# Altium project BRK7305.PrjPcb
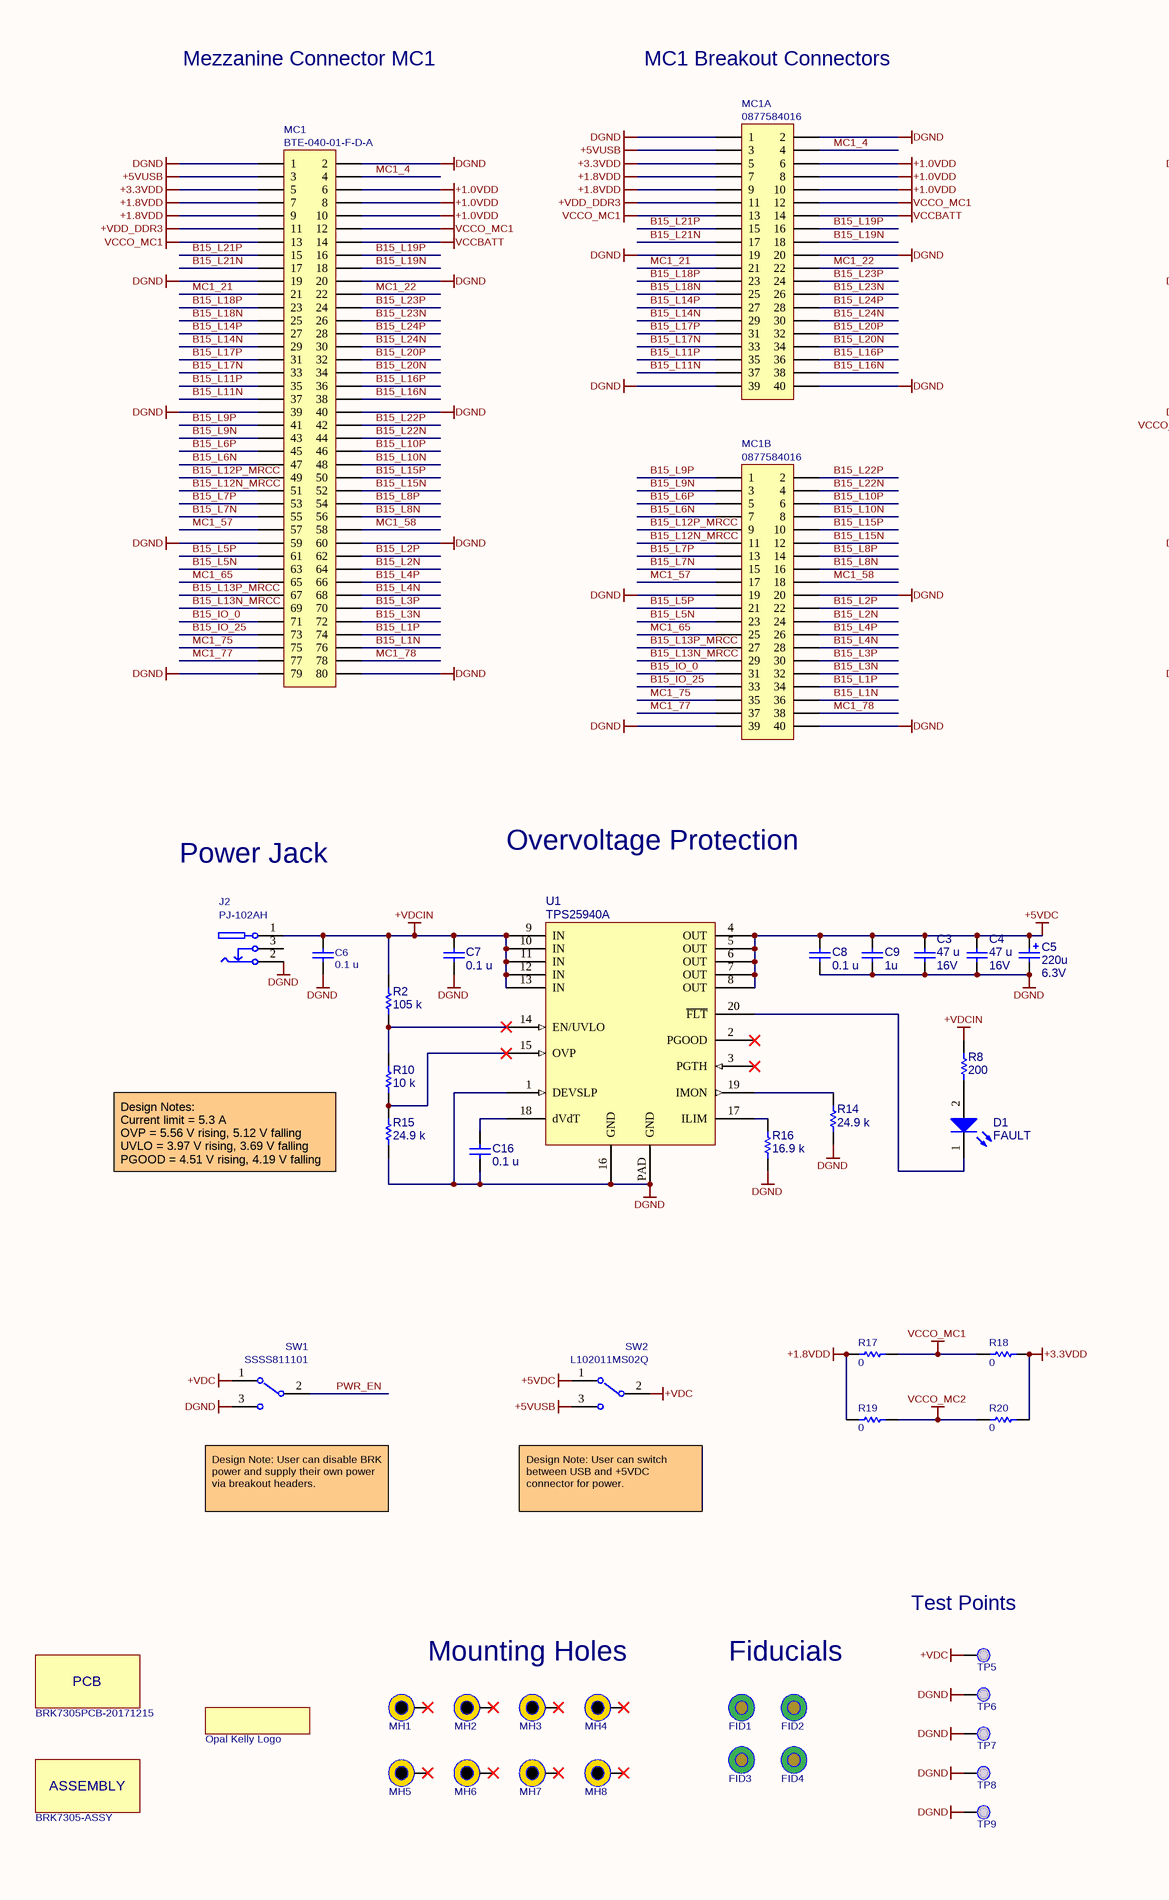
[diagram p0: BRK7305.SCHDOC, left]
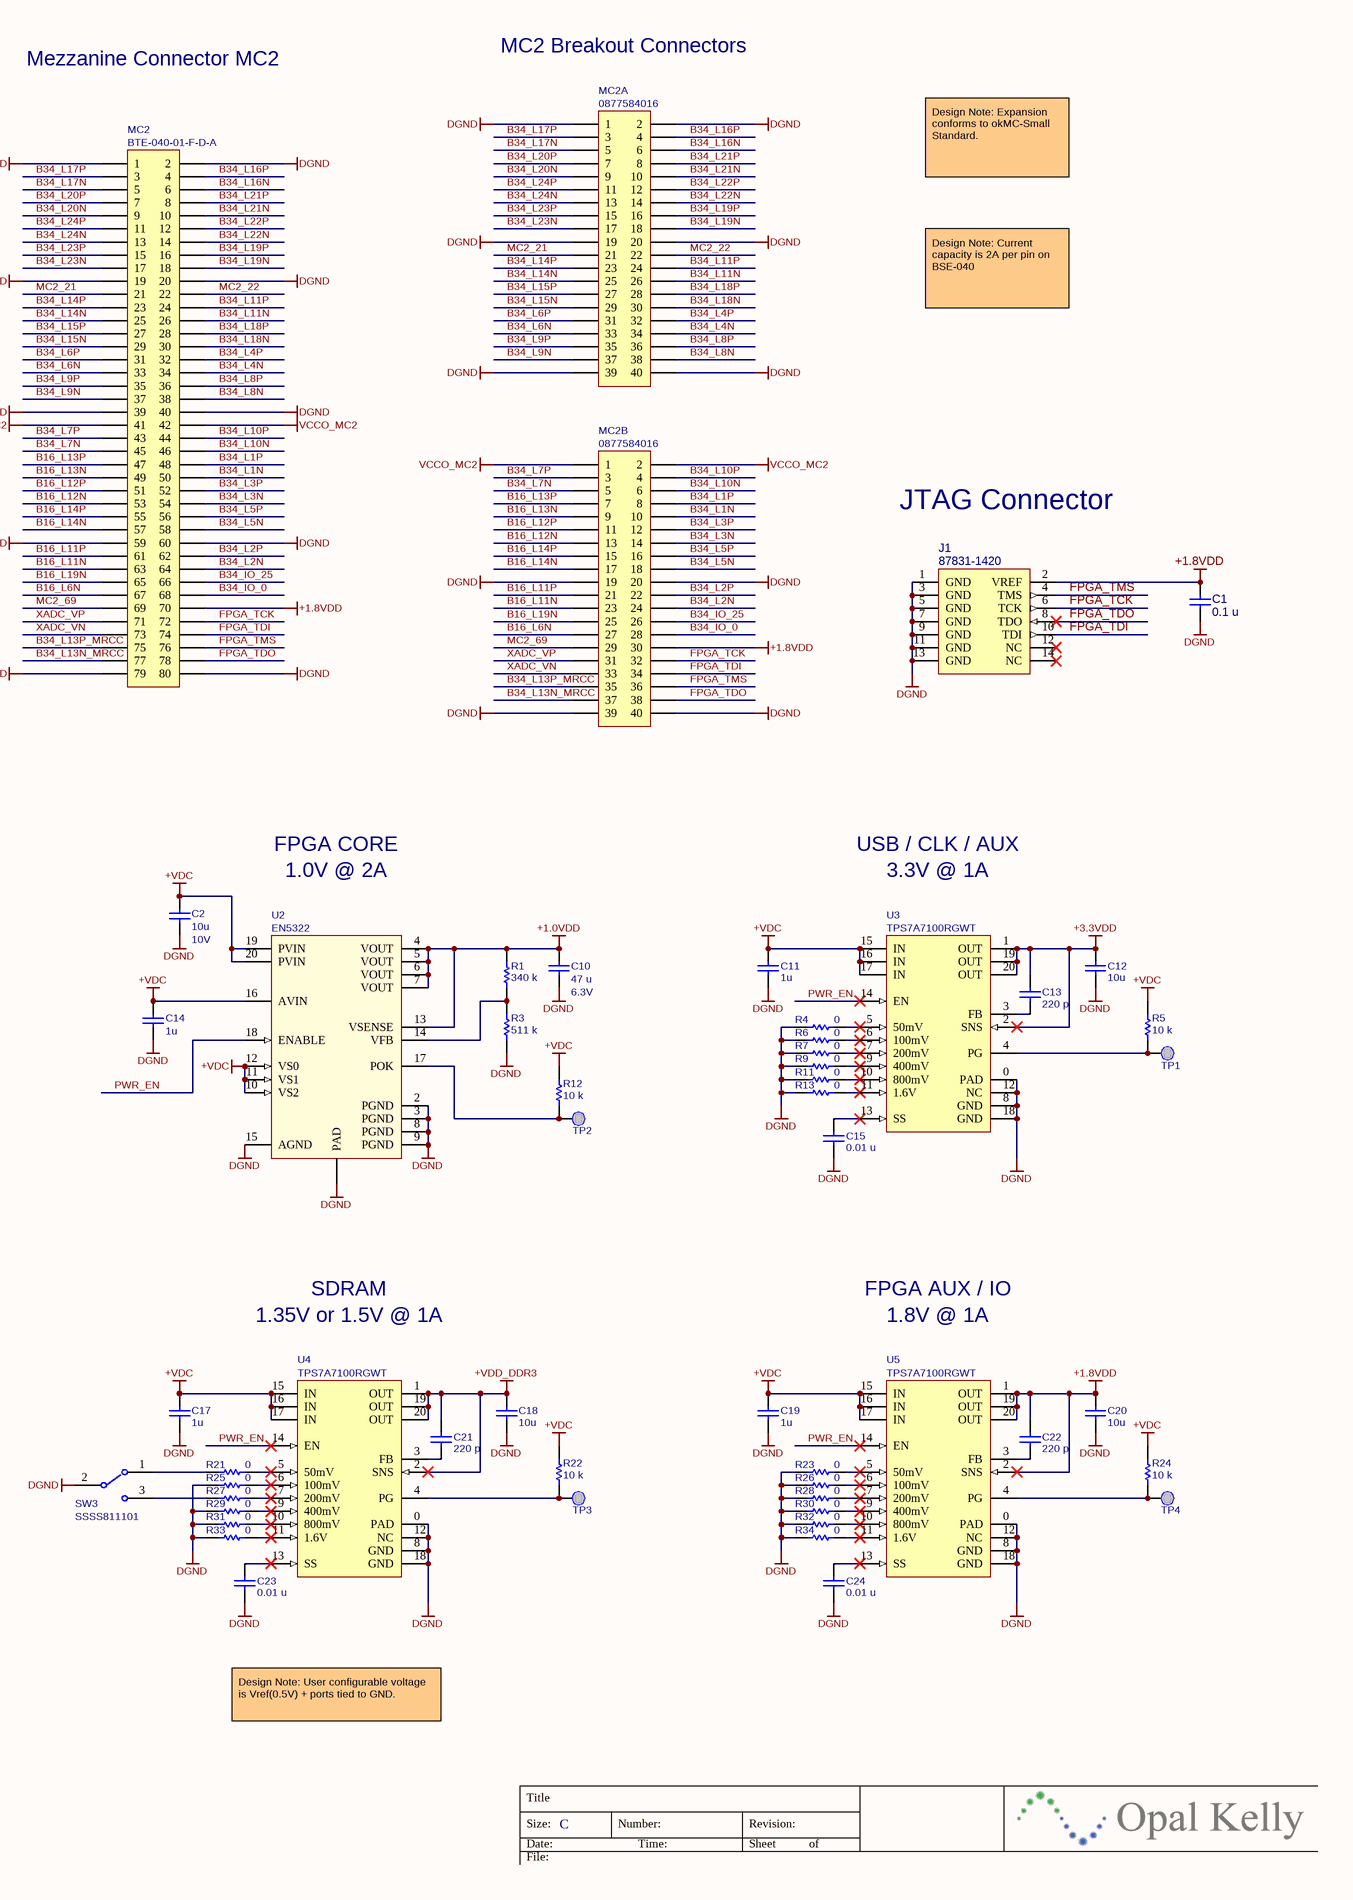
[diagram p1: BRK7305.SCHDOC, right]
Assembly_Part_Num: BRK7305; Assembly_Revision: A01; Assembly_Revision_Major: Axx; PCB_Part_Num: BRK7350PCB; PCB_Revision: 20171215
1 sheet, 99 parts. Net scope: global (net labels, ports and power ports of the same name join across sheets).
Board file: BRK7305.PcbDoc

## Sheet BRK7305.SCHDOC: BRK7305 BreakOut Board
size C; Author: Casey Smith; Organization: Opal Kelly; Address1: 13500 SW 72nd Ave, STE 205; Address2: Portland, OR 97223; Address3: 217.391.3724; Address4: http://www.opalkelly.com; DocumentNumber: xxx; Revision: 1; SheetNumber: 1; SheetTotal: 1

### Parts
*1  Opal Kelly Logo  [okLogo-23x5]
ASSY1  BRK7305-ASSY  (mechanical)
C1  value 0.1 u  [CAPC1608N]  (hidden comment: C0603C104K4RACTU)
C2  value 10u  Voltage: 10V  [CAPC2012N]  (hidden comment: LMK212BJ106KG-T)
C3  value 47 u  Voltage: 16V  [CAPC3225N]  (hidden comment: GRM32ER61C476KE15K)
C4  value 47 u  Voltage: 16V  [CAPC3225N]  (hidden comment: GRM32ER61C476KE15K)
C5  value 220u  Voltage: 6.3V  [CAPAE9083X70N]  (hidden comment: 6SVPS220M)
C6  value 0.1 u  [CAPC1005X06N]  (hidden comment: TMK105BJ104KV-F)
C7  value 0.1 u  [CAPC1608N]  (hidden comment: C0603C104K4RACTU)
C8  value 0.1 u  [CAPC1608N]  (hidden comment: C0603C104K4RACTU)
C9  value 1u  [CAPC1005X06N]  (hidden comment: LMK105BJ105KV-F)
C10  value 47 u  Voltage: 6.3V  [CAPC3216N]  (hidden comment: JMK316BJ476ML-T)
C11  value 1u  [CAPC1005X06N]  (hidden comment: LMK105BJ105KV-F)
C12  value 10u  [CAPC2012X14N]  (hidden comment: LMK212BJ106KG-T)
C13  value 220 p  [CAPC1005X06N]  (hidden comment: C0402C221J5GACTU)
C14  value 1u  [CAPC1005X06N]  (hidden comment: LMK105BJ105KV-F)
C15  value 0.01 u  [CAPC1005X06N]  (hidden comment: C0402C103K4RACTU)
C16  value 0.1 u  [CAPC1608N]  (hidden comment: C0603C104K4RACTU)
C17  value 1u  [CAPC1005X06N]  (hidden comment: LMK105BJ105KV-F)
C18  value 10u  [CAPC2012X14N]  (hidden comment: LMK212BJ106KG-T)
C19  value 1u  [CAPC1005X06N]  (hidden comment: LMK105BJ105KV-F)
C20  value 10u  [CAPC2012X14N]  (hidden comment: LMK212BJ106KG-T)
C21  value 220 p  [CAPC1005X06N]  (hidden comment: C0402C221J5GACTU)
C22  value 220 p  [CAPC1005X06N]  (hidden comment: C0402C221J5GACTU)
C23  value 0.01 u  [CAPC1005X06N]  (hidden comment: C0402C103K4RACTU)
C24  value 0.01 u  [CAPC1005X06N]  (hidden comment: C0402C103K4RACTU)
D1  FAULT  [DIALIGHT-598-0603]
FID1  FIDUCIAL  [FID1MM/2MM-SS]  (value not drawn)
FID2  FIDUCIAL  [FID1MM/2MM-SS]  (value not drawn)
FID3  FIDUCIAL  [FID1MM/2MM-SS]  (value not drawn)
FID4  FIDUCIAL  [FID1MM/2MM-SS]  (value not drawn)
J1  87831-1420  [XILINX-JTAG]
J2  PJ-102AH  [CUI-PJ102A]
MC1  BTE-040-01-F-D-A  [BTE-040]
MC1A  0877584016  [HDR2X20-2MM]
MC1B  0877584016  [HDR2X20-2MM]
MC2  BTE-040-01-F-D-A  [BTE-040]
MC2A  0877584016  [HDR2X20-2MM]
MC2B  0877584016  [HDR2X20-2MM]
MH1  MTG  [MTG-2.5/5.0-PTH]  (value not drawn)
MH2  MTG  [MTG-2.5/5.0-PTH]  (value not drawn)
MH3  MTG  [MTG-2.5/5.0-PTH]  (value not drawn)
MH4  MTG  [MTG-2.5/5.0-PTH]  (value not drawn)
MH5  MTG  [MTG-2.5/5.0-PTH]  (value not drawn)
MH6  MTG  [MTG-2.5/5.0-PTH]  (value not drawn)
MH7  MTG  [MTG-2.5/5.0-PTH]  (value not drawn)
MH8  MTG  [MTG-2.5/5.0-PTH]  (value not drawn)
PCB1  BRK7305PCB-20171215  (mechanical)
R1  value 340 k  [RESC1005X06N]  (hidden comment: CRCW0402340KFKED)
R2  value 105 k  [RESC1005X06N]  (hidden comment: CRCW0402105KFKED)
R3  value 511 k  [RESC1005X06N]  (hidden comment: CRCW0402511KFKED)
R4  value 0  [RESC1005X06N]  (hidden comment: CRCW04020000Z0ED)
R5  value 10 k  [RESC1005X06N]  (hidden comment: CRCW040210K0JNED)
R6  value 0  [RESC1005X06N]  (hidden comment: CRCW04020000Z0ED)
R7  value 0  [RESC1005X06N]  (hidden comment: CRCW04020000Z0ED)
R8  value 200  [RESC1005X06N]  (hidden comment: CRCW0402200RFKED)
R9  value 0  [RESC1005X06N]  (hidden comment: CRCW04020000Z0ED)
R10  value 10 k  [RESC1005X06N]  (hidden comment: CRCW040210K0JNED)
R11  value 0  [RESC1005X06N]  (hidden comment: CRCW04020000Z0ED)
R12  value 10 k  [RESC1005X06N]  (hidden comment: CRCW040210K0JNED)
R13  value 0  [RESC1005X06N]  (hidden comment: CRCW04020000Z0ED)
R14  value 24.9 k  [RESC1005X06N]  (hidden comment: CRCW040224K9FKED)
R15  value 24.9 k  [RESC1005X06N]  (hidden comment: CRCW040224K9FKED)
R16  value 16.9 k  [RESC1005X06N]  (hidden comment: CRCW040216K9FKED)
R17  value 0  [RESC1608N]  (hidden comment: CRCW06030000Z0EA)
R18  value 0  [RESC1608N]  (hidden comment: CRCW06030000Z0EA)
R19  value 0  [RESC1608N]  (hidden comment: CRCW06030000Z0EA)
R20  value 0  [RESC1608N]  (hidden comment: CRCW06030000Z0EA)
R21  value 0  [RESC1005X06N]  (hidden comment: CRCW04020000Z0ED)
R22  value 10 k  [RESC1005X06N]  (hidden comment: CRCW040210K0JNED)
R23  value 0  [RESC1005X06N]  (hidden comment: CRCW04020000Z0ED)
R24  value 10 k  [RESC1005X06N]  (hidden comment: CRCW040210K0JNED)
R25  value 0  [RESC1005X06N]  (hidden comment: CRCW04020000Z0ED)
R26  value 0  [RESC1005X06N]  (hidden comment: CRCW04020000Z0ED)
R27  value 0  [RESC1005X06N]  (hidden comment: CRCW04020000Z0ED)
R28  value 0  [RESC1005X06N]  (hidden comment: CRCW04020000Z0ED)
R29  value 0  [RESC1005X06N]  (hidden comment: CRCW04020000Z0ED)
R30  value 0  [RESC1005X06N]  (hidden comment: CRCW04020000Z0ED)
R31  value 0  [RESC1005X06N]  (hidden comment: CRCW04020000Z0ED)
R32  value 0  [RESC1005X06N]  (hidden comment: CRCW04020000Z0ED)
R33  value 0  [RESC1005X06N]  (hidden comment: CRCW04020000Z0ED)
R34  value 0  [RESC1005X06N]  (hidden comment: CRCW04020000Z0ED)
SW1  SSSS811101  [SSSS811101]
SW2  L102011MS02Q  [L102011MS]
SW3  SSSS811101  [SSSS811101]
TP1  +3.3VDD_PG  [TP-PTH-25/45]  (value not drawn)
TP2  +1.8VDD_PG  [TP-PTH-25/45]  (value not drawn)
TP3  +VDD_DDR3_PG  [TP-PTH-25/45]  (value not drawn)
TP4  +1.8VDD_PG  [TP-PTH-25/45]  (value not drawn)
TP5  +VDC  [TP-PTH-25/45]  (value not drawn)
TP6  DGND  [TP-PTH-25/45]  (value not drawn)
TP7  DGND  [TP-PTH-25/45]  (value not drawn)
TP8  DGND  [TP-PTH-25/45]  (value not drawn)
TP9  DGND  [TP-PTH-25/45]  (value not drawn)
U1  TPS25940A  [TPS25940]
U2  EN5322  [EN5322QI]
U3  TPS7A7100RGWT  [S-PVQN-N20]
U4  TPS7A7100RGWT  [S-PVQN-N20]
U5  TPS7A7100RGWT  [S-PVQN-N20]

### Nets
+1.0VDD: C10.2 MC1.6 MC1.8 MC1.10 MC1A.6 MC1A.8 MC1A.10 R1.2 U2.4(VOUT) U2.5(VOUT) U2.6(VOUT) U2.7(VOUT) U2.13(VSENSE)
+1.8VDD: C1.2 C20.2 C22.2 J1.2(VREF) MC1.7 MC1.9 MC1A.7 MC1A.9 MC2.70 MC2B.30 R17.1 R19.1 U5.1(OUT) U5.2(SNS) U5.19(OUT) U5.20(OUT)
+3.3VDD: C12.2 C13.2 MC1.5 MC1A.5 R18.2 R20.2 U3.1(OUT) U3.2(SNS) U3.19(OUT) U3.20(OUT)
+5VDC: C3.1 C4.1 C5.1 C8.2 C9.2 SW2.1 U1.4(OUT) U1.5(OUT) U1.6(OUT) U1.7(OUT) U1.8(OUT)
+5VUSB: MC1.3 MC1A.3 SW2.3
+VDC: C2.2 C11.2 C14.2 C17.2 C19.2 R5.2 R12.2 R22.2 R24.2 SW1.1 SW2.2 TP5.1(PIN) U2.10(VS2) U2.11(VS1) U2.12(VS0) U2.16(AVIN) U2.19(PVIN) U2.20(PVIN) U3.15(IN) U3.16(IN) U3.17(IN) U4.15(IN) U4.16(IN) U4.17(IN) U5.15(IN) U5.16(IN) U5.17(IN)
+VDCIN: C6.2 C7.2 J2.1 R2.2 R8.2 U1.9(IN) U1.10(IN) U1.11(IN) U1.12(IN) U1.13(IN)
+VDD_DDR3: C18.2 C21.2 MC1.11 MC1A.11 U4.1(OUT) U4.2(SNS) U4.19(OUT) U4.20(OUT)
DGND: C1.1 C2.1 C3.2 C4.2 C5.2 C6.1 C7.1 C8.1 C9.1 C10.1 C11.1 C12.1 C14.1 C15.1 C16.1 C17.1 C18.1 C19.1 C20.1 C23.1 C24.1 J1.1(GND) J1.3(GND) J1.5(GND) J1.7(GND) J1.9(GND) J1.11(GND) J1.13(GND) J2.2 MC1.1 MC1.2 MC1.19 MC1.20 MC1.39 MC1.40 MC1.59 MC1.60 MC1.79 MC1.80 MC1A.1 MC1A.2 MC1A.19 MC1A.20 MC1A.39 MC1A.40 MC1B.19 MC1B.20 MC1B.39 MC1B.40 MC2.1 MC2.2 MC2.19 MC2.20 MC2.39 MC2.40 MC2.59 MC2.60 MC2.79 MC2.80 MC2A.1 MC2A.2 MC2A.19 MC2A.20 MC2A.39 MC2A.40 MC2B.19 MC2B.20 MC2B.39 MC2B.40 R3.1 R4.1 R6.1 R7.1 R9.1 R11.1 R13.1 R14.1 R15.1 R16.1 R23.1 R25.1 R26.1 R28.1 R29.1 R30.1 R31.1 R32.1 R33.1 R34.1 SW1.3 SW3.2 TP6.1(PIN) TP7.1(PIN) TP8.1(PIN) TP9.1(PIN) U1.1(DEVSLP) U1.16(GND) U1.PAD(GND) U2.2(PGND) U2.3(PGND) U2.8(PGND) U2.9(PGND) U2.15(AGND) U2.PAD U3.0(PAD) U3.8(GND) U3.12(NC) U3.18(GND) U4.0(PAD) U4.8(GND) U4.12(NC) U4.18(GND) U5.0(PAD) U5.8(GND) U5.12(NC) U5.18(GND)
VCCBATT: MC1.14 MC1A.14
VCCO_MC1: MC1.12 MC1.13 MC1A.12 MC1A.13 R17.2 R18.1
VCCO_MC2: MC2.41 MC2.42 MC2B.1 MC2B.2 R19.2 R20.1
B15_IO_0: MC1.71 MC1B.31
B15_IO_25: MC1.73 MC1B.33
B15_L1N: MC1.76 MC1B.36
B15_L1P: MC1.74 MC1B.34
B15_L2N: MC1.64 MC1B.24
B15_L2P: MC1.62 MC1B.22
B15_L3N: MC1.72 MC1B.32
B15_L3P: MC1.70 MC1B.30
B15_L4N: MC1.68 MC1B.28
B15_L4P: MC1.66 MC1B.26
B15_L5N: MC1.63 MC1B.23
B15_L5P: MC1.61 MC1B.21
B15_L6N: MC1.47 MC1B.7
B15_L6P: MC1.45 MC1B.5
B15_L7N: MC1.55 MC1B.15
B15_L7P: MC1.53 MC1B.13
B15_L8N: MC1.56 MC1B.16
B15_L8P: MC1.54 MC1B.14
B15_L9N: MC1.43 MC1B.3
B15_L9P: MC1.41 MC1B.1
B15_L10N: MC1.48 MC1B.8
B15_L10P: MC1.46 MC1B.6
B15_L11N: MC1.37 MC1A.37
B15_L11P: MC1.35 MC1A.35
B15_L12N_MRCC: MC1.51 MC1B.11
B15_L12P_MRCC: MC1.49 MC1B.9
B15_L13N_MRCC: MC1.69 MC1B.29
B15_L13P_MRCC: MC1.67 MC1B.27
B15_L14N: MC1.29 MC1A.29
B15_L14P: MC1.27 MC1A.27
B15_L15N: MC1.52 MC1B.12
B15_L15P: MC1.50 MC1B.10
B15_L16N: MC1.38 MC1A.38
B15_L16P: MC1.36 MC1A.36
B15_L17N: MC1.33 MC1A.33
B15_L17P: MC1.31 MC1A.31
B15_L18N: MC1.25 MC1A.25
B15_L18P: MC1.23 MC1A.23
B15_L19N: MC1.18 MC1A.18
B15_L19P: MC1.16 MC1A.16
B15_L20N: MC1.34 MC1A.34
B15_L20P: MC1.32 MC1A.32
B15_L21N: MC1.17 MC1A.17
B15_L21P: MC1.15 MC1A.15
B15_L22N: MC1.44 MC1B.4
B15_L22P: MC1.42 MC1B.2
B15_L23N: MC1.26 MC1A.26
B15_L23P: MC1.24 MC1A.24
B15_L24N: MC1.30 MC1A.30
B15_L24P: MC1.28 MC1A.28
B16_L6N: MC2.67 MC2B.27
B16_L11N: MC2.63 MC2B.23
B16_L11P: MC2.61 MC2B.21
B16_L12N: MC2.53 MC2B.13
B16_L12P: MC2.51 MC2B.11
B16_L13N: MC2.49 MC2B.9
B16_L13P: MC2.47 MC2B.7
B16_L14N: MC2.57 MC2B.17
B16_L14P: MC2.55 MC2B.15
B16_L19N: MC2.65 MC2B.25
B34_IO_0: MC2.68 MC2B.28
B34_IO_25: MC2.66 MC2B.26
B34_L1N: MC2.50 MC2B.10
B34_L1P: MC2.48 MC2B.8
B34_L2N: MC2.64 MC2B.24
B34_L2P: MC2.62 MC2B.22
B34_L3N: MC2.54 MC2B.14
B34_L3P: MC2.52 MC2B.12
B34_L4N: MC2.34 MC2A.34
B34_L4P: MC2.32 MC2A.32
B34_L5N: MC2.58 MC2B.18
B34_L5P: MC2.56 MC2B.16
B34_L6N: MC2.33 MC2A.33
B34_L6P: MC2.31 MC2A.31
B34_L7N: MC2.45 MC2B.5
B34_L7P: MC2.43 MC2B.3
B34_L8N: MC2.38 MC2A.38
B34_L8P: MC2.36 MC2A.36
B34_L9N: MC2.37 MC2A.37
B34_L9P: MC2.35 MC2A.35
B34_L10N: MC2.46 MC2B.6
B34_L10P: MC2.44 MC2B.4
B34_L11N: MC2.26 MC2A.26
B34_L11P: MC2.24 MC2A.24
B34_L13N_MRCC: MC2.77 MC2B.37
B34_L13P_MRCC: MC2.75 MC2B.35
B34_L14N: MC2.25 MC2A.25
B34_L14P: MC2.23 MC2A.23
B34_L15N: MC2.29 MC2A.29
B34_L15P: MC2.27 MC2A.27
B34_L16N: MC2.6 MC2A.6
B34_L16P: MC2.4 MC2A.4
B34_L17N: MC2.5 MC2A.5
B34_L17P: MC2.3 MC2A.3
B34_L18N: MC2.30 MC2A.30
B34_L18P: MC2.28 MC2A.28
B34_L19N: MC2.18 MC2A.18
B34_L19P: MC2.16 MC2A.16
B34_L20N: MC2.9 MC2A.9
B34_L20P: MC2.7 MC2A.7
B34_L21N: MC2.10 MC2A.10
B34_L21P: MC2.8 MC2A.8
B34_L22N: MC2.14 MC2A.14
B34_L22P: MC2.12 MC2A.12
B34_L23N: MC2.17 MC2A.17
B34_L23P: MC2.15 MC2A.15
B34_L24N: MC2.13 MC2A.13
B34_L24P: MC2.11 MC2A.11
FPGA_TCK: J1.6(TCK) MC2.72 MC2B.32
FPGA_TDI: J1.10(TDI) MC2.74 MC2B.34
FPGA_TDO: J1.8(TDO) MC2.78 MC2B.38
FPGA_TMS: J1.4(TMS) MC2.76 MC2B.36
MC1_4: MC1.4 MC1A.4
MC1_21: MC1.21 MC1A.21
MC1_22: MC1.22 MC1A.22
MC1_57: MC1.57 MC1B.17
MC1_58: MC1.58 MC1B.18
MC1_65: MC1.65 MC1B.25
MC1_75: MC1.75 MC1B.35
MC1_77: MC1.77 MC1B.37
MC1_78: MC1.78 MC1B.38
MC2_21: MC2.21 MC2A.21
MC2_22: MC2.22 MC2A.22
MC2_69: MC2.69 MC2B.29
PWR_EN: SW1.2 U2.18(ENABLE) U3.14(EN) U4.14(EN) U5.14(EN)
XADC_VN: MC2.73 MC2B.33
XADC_VP: MC2.71 MC2B.31
NetC13_1: C13.1 U3.3(FB)
NetC15_2: C15.2 U3.13(SS)
NetC16_2: C16.2 U1.18(dVdT)
NetC21_1: C21.1 U4.3(FB)
NetC22_1: C22.1 U5.3(FB)
NetC23_2: C23.2 U4.13(SS)
NetC24_2: C24.2 U5.13(SS)
NetD1_1: D1.1(K) U1.20(~{FLT})
NetD1_2: D1.2(A) R8.1
NetR1_1: R1.1 R3.2 U2.14(VFB)
NetR2_1: R2.1 R10.2 U1.14(EN/UVLO)
NetR4_2: R4.2 U3.5(50mV)
NetR5_1: R5.1 TP1.1(PIN) U3.4(PG)
NetR6_2: R6.2 U3.6(100mV)
NetR7_2: R7.2 U3.7(200mV)
NetR9_2: R9.2 U3.9(400mV)
NetR10_1: R10.1 R15.2 U1.15(OVP)
NetR11_2: R11.2 U3.10(800mV)
NetR12_1: R12.1 TP2.1(PIN) U2.17(POK)
NetR13_2: R13.2 U3.11(1.6V)
NetR14_2: R14.2 U1.19(IMON)
NetR16_2: R16.2 U1.17(ILIM)
NetR21_1: R21.1 SW3.1
NetR21_2: R21.2 U4.5(50mV)
NetR22_1: R22.1 TP3.1(PIN) U4.4(PG)
NetR23_2: R23.2 U5.5(50mV)
NetR24_1: R24.1 TP4.1(PIN) U5.4(PG)
NetR25_2: R25.2 U4.6(100mV)
NetR26_2: R26.2 U5.6(100mV)
NetR27_1: R27.1 SW3.3
NetR27_2: R27.2 U4.7(200mV)
NetR28_2: R28.2 U5.7(200mV)
NetR29_2: R29.2 U4.9(400mV)
NetR30_2: R30.2 U5.9(400mV)
NetR31_2: R31.2 U4.10(800mV)
NetR32_2: R32.2 U5.10(800mV)
NetR33_2: R33.2 U4.11(1.6V)
NetR34_2: R34.2 U5.11(1.6V)

Not connected (* = marked no-connect by the designer): J1 12(NC)* 14(NC)*; J2 3; MH1 1*; MH2 1*; MH3 1*; MH4 1*; MH5 1*; MH6 1*; MH7 1*; MH8 1*; U1 2(PGOOD)* 3(PGTH)*

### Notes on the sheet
- Mezzanine Connector MC1
- MC1 Breakout Connectors
- Mezzanine Connector MC2
- MC2 Breakout Connectors
- Design Note: Expansion conforms to okMC-Small Standard.
- Design Note: Current capacity is 2A per pin on BSE-040
- JTAG Connector
- Power Jack
- Overvoltage Protection
- FPGA CORE
- 1.0V @ 2A
- USB / CLK / AUX
- 3.3V @ 1A
- Design Notes:
  Current limit = 5.3 A
  OVP = 5.56 V rising, 5.12 V falling
  UVLO = 3.97 V rising, 3.69 V falling
  PGOOD = 4.51 V rising, 4.19 V falling
- SDRAM
- 1.35V or 1.5V @ 1A
- FPGA AUX / IO
- 1.8V @ 1A
- (near SW1) Design Note: User can disable BRK power and supply their own power via breakout headers.
- (near SW2) Design Note: User can switch between USB and +5VDC connector for power.
- Mounting Holes
- Fiducials
- (near TP5) Test Points
- Design Note: User configurable voltage is Vref(0.5V) + ports tied to GND.
- Title
- Size:
- Date:
- File:
- C
- Number:
- Time:
- Revision:
- Sheet
- of

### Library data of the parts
*1 = OKLOGO
ASSY1 = 001675: BRK7305 PCB assembly; Manufacturer: PCB Assembly Cost; partnumber: 001675
C1 C7 C8 = 000019: Ceramic capacitor; Manufacturer: Kemet; partnumber: 000019; Description 2: SM-0603, 10%, 16v, X7R; ValueFloat: 1E-7
C2 = 000491: Ceramic capacitor; Manufacturer: Taiyo Yuden; partnumber: 000491; Description 2: SM-0805, 10%, 10v; ValueFloat: 1E-5; Tolerance (%): 10
C3 C4 = 001368: Ceramic Capacitor; Manufacturer: Murata; partnumber: 001368; Description 2: 1210, 16V, 10%; ValueFloat: 4.7E-5; Tolerance (%): 10; x_voltage-rating: 16; x_lifecycle_status: Production
C5 = 001384: Capacitor, Solid Polymer Aluminum, 220uF, 6.3V, 8mm dia, 22mOhm; Manufacturer: Panasonic; partnumber: 001384; ValueFloat: 0.00022; Tolerance (%): 20; x_voltage-rating: 6.3; x_lifecycle_status: Production
C6 = 001073: Ceramic capacitor; Manufacturer: Taiyo Yuden; partnumber: 001073; Description 2: 0402, 25V; ValueFloat: 1E-7; Tolerance (%): 10; Voltage: 25V
C9 C11 C14 C17 C19 = 000480: Ceramic capacitor; Manufacturer: Taiyo Yuden; partnumber: 000480; Description 2: SM-0402, 10%, 10v; ValueFloat: 1E-6; Tolerance (%): 10
C10 = 000570: Ceramic Capacitor; Manufacturer: Taiyo Yuden; partnumber: 000570; Description 2: 1206, 6.3V; ValueFloat: 4.7E-5; Tolerance (%): 20
C12 C18 C20 = 000491: Ceramic capacitor; Manufacturer: Taiyo Yuden; partnumber: 000491; Description 2: SM-0805, 10%, 10v; ValueFloat: 1E-5; Tolerance (%): 10; x_lifecycle_status: Production
C13 C21 C22 = 001219: Ceramic capacitor; Manufacturer: Kemet; partnumber: 001219; Description 2: SM-0402, 5%, 50v; ValueFloat: 2.2E-10; Tolerance (%): 5
C15 C23 C24 = 000295: Ceramic Capacitor; Manufacturer: Kemet; partnumber: 000295; Description 2: SM-0402, 10%, 6.3V, X5R; ValueFloat: 1E-8; Tolerance (%): 10
C16 = 000019: Ceramic capacitor; Manufacturer: Kemet; partnumber: 000019; Description 2: SM-0603, 10%, 16v, X7R; ValueFloat: 1E-7; x_lifecycle_status: Production
D1 = 001432: LED; Manufacturer: Dialight; Manufacturer_PN: 598-8010-107F; partnumber: 001432; Description 2: SM-0603, red; x_lifecycle_status: Production
FID1-FID4 = FIDUCIAL: PCB fiducial
J1 = 000541: 2mm header, shrouded; Manufacturer: Molex; partnumber: 000541; Description 2: Dual-row, 14-pos, Xilinx JTAG compatible
J2 = 000356: DC power connector - high current; Manufacturer: CUI Inc.; partnumber: 000356; Description 2: 2.1mm / 5.5mm
MC1 MC2 = 000059: 0.8mm high-density header; Manufacturer: Samtec; partnumber: 000059; Description 2: 80-pin, Gold flash, Mated height: 5.00mm (0.197 inch)
MC1A MC1B MC2A MC2B = 000583: 2mm header, 20x2, thru-hole; Manufacturer: Molex; partnumber: 000583
MH1-MH8 = MTG: Mounting hole
PCB1 = 001676: PCB for BRK5305; Manufacturer: Generic PCB Manufacturer; partnumber: 001676; x_lifecycle_status: Production
R1 = 001234: Thick-film resistor; Manufacturer: Vishay; partnumber: 001234; Description 2: SM-0402, 1%, 1/16W; ValueFloat: 340000; Tolerance (%): 1
R2 = 001124: Thick-film resistor; Manufacturer: Vishay; partnumber: 001124; Description 2: SM-0402, 1%, 1/16W; ValueFloat: 105000; Tolerance (%): 1
R3 = 001409: Thick-film resistor; Manufacturer: Vishay; partnumber: 001409; Description 2: SM-0402, 1%, 1/16W; ValueFloat: 511000; Tolerance (%): 1; x_lifecycle_status: Production
R4 R6 R7 R9 R11 R13 R21 R23 R25-R34 = 000755: Thick-film resistor; Manufacturer: Vishay; partnumber: 000755; Description 2: SM-0402, 1%, 1/16W; Tolerance (%): 1
R5 R10 R12 R22 R24 = 000759: Thick-film resistor; Manufacturer: Vishay; partnumber: 000759; Description 2: SM-0402, 5%, 1/16W; ValueFloat: 10000; Tolerance (%): 5
R8 = 000780: Thick-film resistor; Manufacturer: Vishay; partnumber: 000780; Description 2: SM-0402, 1%, 1/16W; Tolerance (%): 1
R14 R15 = 000934: Thick-film resistor; Manufacturer: Vishay; partnumber: 000934; Description 2: SM-0402, 1%, 1/16W; ValueFloat: 24900; Tolerance (%): 1
R16 = 001332: Thick-film resistor; Manufacturer: Vishay; partnumber: 001332; Description 2: SM-0402, 1%, 1/16W; ValueFloat: 16900; Tolerance (%): 1
R17-R20 = 000411: Zero-ohm resistor; Manufacturer: Vishay; partnumber: 000411; Description 2: SM-0603, 1/10W, 20 mOhm max, 2.0 A max
SW1 SW3 = 000231: Slide; Manufacturer: Alps; partnumber: 000231; Description 2: 1 position, 2 pole, SMT slide switch
SW2 = 001220: SPDT; Manufacturer: C&K Components; partnumber: 001220; Description 2: PC Thru-Hole Mount, PC Thru-Hole Termination
TP1-TP9 = TP-PTH-25/45: Test point, plated through-hole, 25/45mil
U1 = 001325: 18V eFuse with reverse- /over-voltage protection and current limiting, auto-retry; Manufacturer: Texas Instruments; partnumber: 001325; Description 2: 2.7V-18V, 5.3A current limit, 42 mOhm R_ON, 3x4mm WQFN-20; x_lifecycle_status: Production
U2 = 000477: 2A Synchronous Buck DC-DC converter; PartNumber: 000477; Manufacturer: Altera; Description 2: 2.4v - 5.5v input, 4MHz switching; x_lifecycle_status: Production
U3-U5 = 001209: LDO voltage regulator; Manufacturer: Texas Instruments; partnumber: 001209; Description 2: Vin: 1.5V-6.5V Vout Fixed: 0.9V-3.5V Vout Adj:0,9V-5V

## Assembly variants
Default: not fitted MC1A MC1B MC2A MC2B R4 R6 R7 R14 R17 R19 R23 R25 R28 R29 R33 R34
